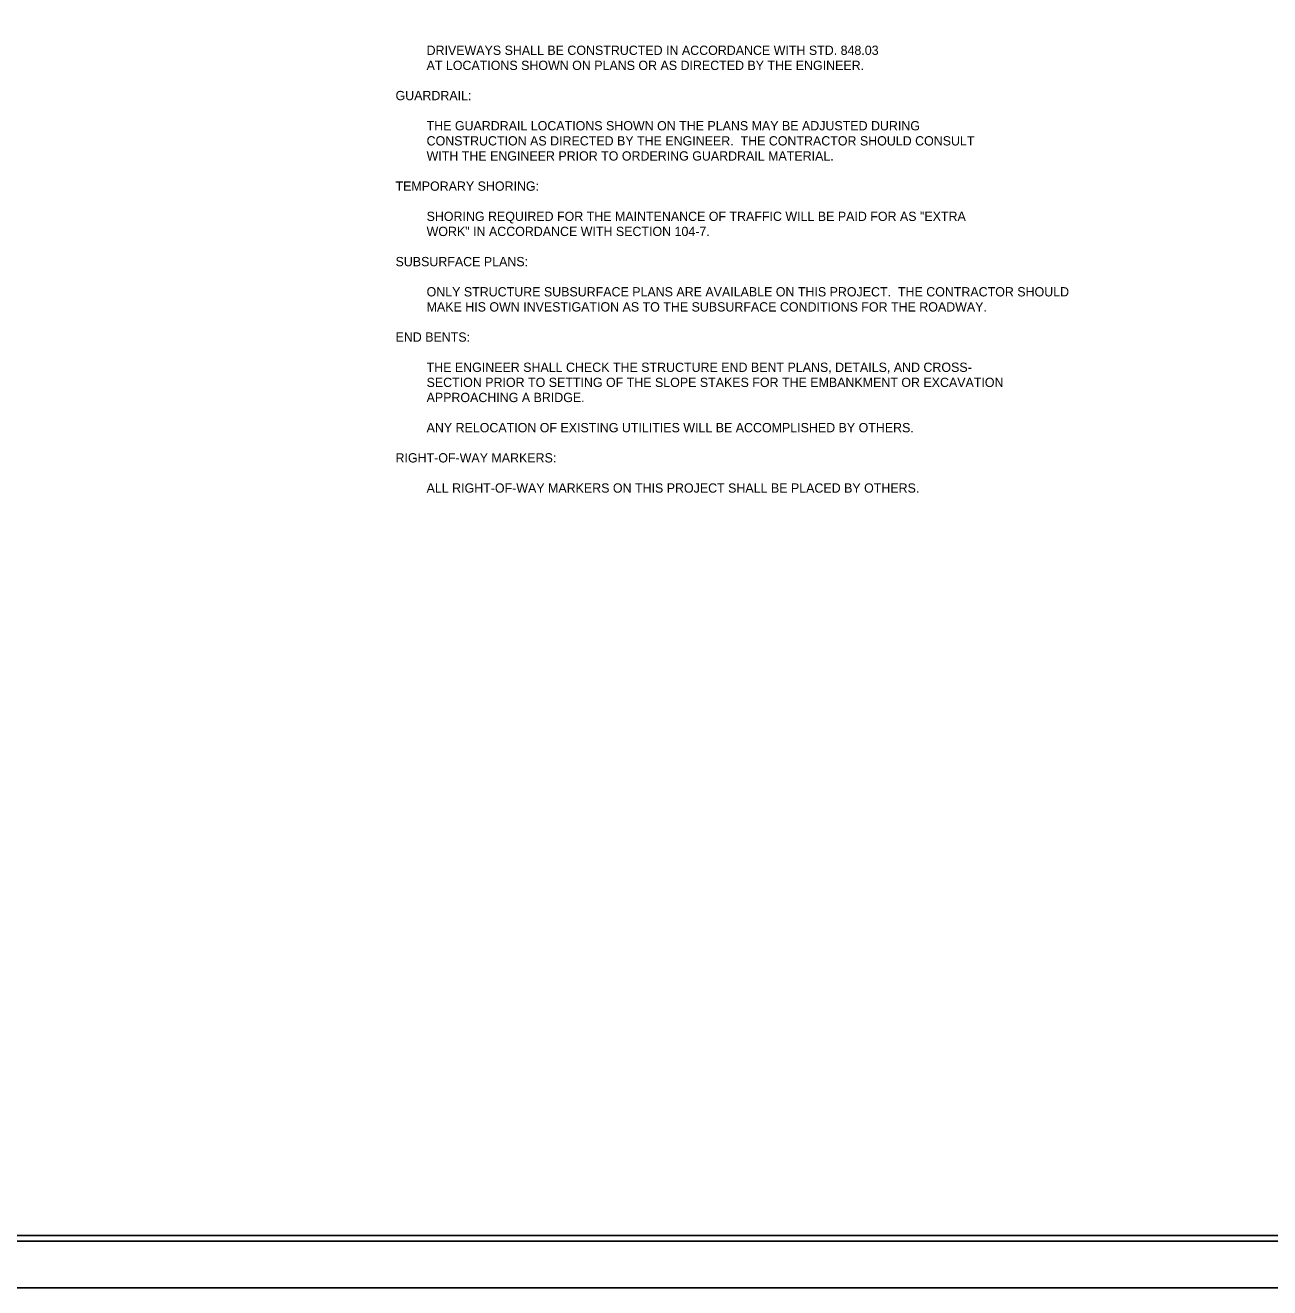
# Model space of a CAD drawing. Extents: x 1983800 to 2121016, y 627229 to 697309.
# Drawn here: x 2018104 to 2052408, y 627229 to 662023 of the extents above; entities that cross this region are included whole.
import ezdxf

# ---------------------------------------------------------------- set-up
doc = ezdxf.new("R2010")
doc.units = 0
for name, color, linetype in [('Sheet Cutting Line CELL', 7, 'Continuous'), ('Sheet Data Text CELL', 7, 'Continuous'), ('Sheet Plan CELL', 7, 'Continuous'), ('Sheet Plot Border Inside CELL', 7, 'Continuous'), ('Sheet Plot Border Outside CELL', 7, 'Continuous')]:
    doc.layers.add(name, color=color, linetype=linetype)

msp = doc.modelspace()

# ---------------------------------------------------------------- linework, layer by layer
at = {"layer": 'Sheet Cutting Line CELL'}
msp.add_line((1983800, 627229), (2091544, 627229), dxfattribs=at)
at = {"layer": 'Sheet Plan CELL'}
msp.add_lwpolyline([(2090456, 695869), (1994456, 695869), (1994456, 628669), (2090456, 628669)], close=True, dxfattribs=at)
at = {"layer": 'Sheet Plot Border Inside CELL'}
msp.add_lwpolyline([(1984632, 628509), (2091256, 628509), (2091256, 696029), (1984632, 696029)], close=True, dxfattribs=at)
at = {"layer": 'Sheet Plot Border Outside CELL'}
msp.add_lwpolyline([(1983800, 627229), (2091544, 627229), (2091544, 697309), (1983800, 697309)], close=True, dxfattribs=at)

# ---------------------------------------------------------------- texts
at = {"layer": 'Sheet Data Text CELL'}
for s, p in [('         DRIVEWAYS SHALL BE CONSTRUCTED IN ACCORDANCE WITH STD. 848.03', (2028311, 661205)), ('         AT LOCATIONS SHOWN ON PLANS OR AS DIRECTED BY THE ENGINEER.  ', (2028311, 660789)), ('GUARDRAIL:  ', (2028311, 659957)), ('         THE GUARDRAIL LOCATIONS SHOWN ON THE PLANS MAY BE ADJUSTED DURING ', (2028311, 659125)), ('         CONSTRUCTION AS DIRECTED BY THE ENGINEER.  THE CONTRACTOR SHOULD CONSULT', (2028311, 658709)), ('         WITH THE ENGINEER PRIOR TO ORDERING GUARDRAIL MATERIAL.', (2028311, 658293)), ('TEMPORARY SHORING:  ', (2028311, 657461)), ('         SHORING REQUIRED FOR THE MAINTENANCE OF TRAFFIC WILL BE PAID FOR AS "EXTRA ', (2028311, 656629)), ('         WORK" IN ACCORDANCE WITH SECTION 104-7.  ', (2028311, 656213)), ('SUBSURFACE PLANS:  ', (2028311, 655381)), ('         ONLY STRUCTURE SUBSURFACE PLANS ARE AVAILABLE ON THIS PROJECT.  THE CONTRACTOR SHOULD ', (2028311, 654549)), ('         MAKE HIS OWN INVESTIGATION AS TO THE SUBSURFACE CONDITIONS FOR THE ROADWAY.  ', (2028311, 654133)), ('END BENTS:  ', (2028311, 653301)), ('         THE ENGINEER SHALL CHECK THE STRUCTURE END BENT PLANS, DETAILS, AND CROSS-', (2028311, 652469)), ('         SECTION PRIOR TO SETTING OF THE SLOPE STAKES FOR THE EMBANKMENT OR EXCAVATION ', (2028311, 652053)), ('         APPROACHING A BRIDGE.  ', (2028311, 651637)), ('         ANY RELOCATION OF EXISTING UTILITIES WILL BE ACCOMPLISHED BY OTHERS.  ', (2028311, 650805)), ('RIGHT-OF-WAY MARKERS:  ', (2028311, 649973)), ('         ALL RIGHT-OF-WAY MARKERS ON THIS PROJECT SHALL BE PLACED BY OTHERS.', (2028311, 649141))]:
    msp.add_text(s, height=256, dxfattribs=at).set_placement(p)

doc.saveas('drawing.dxf')
